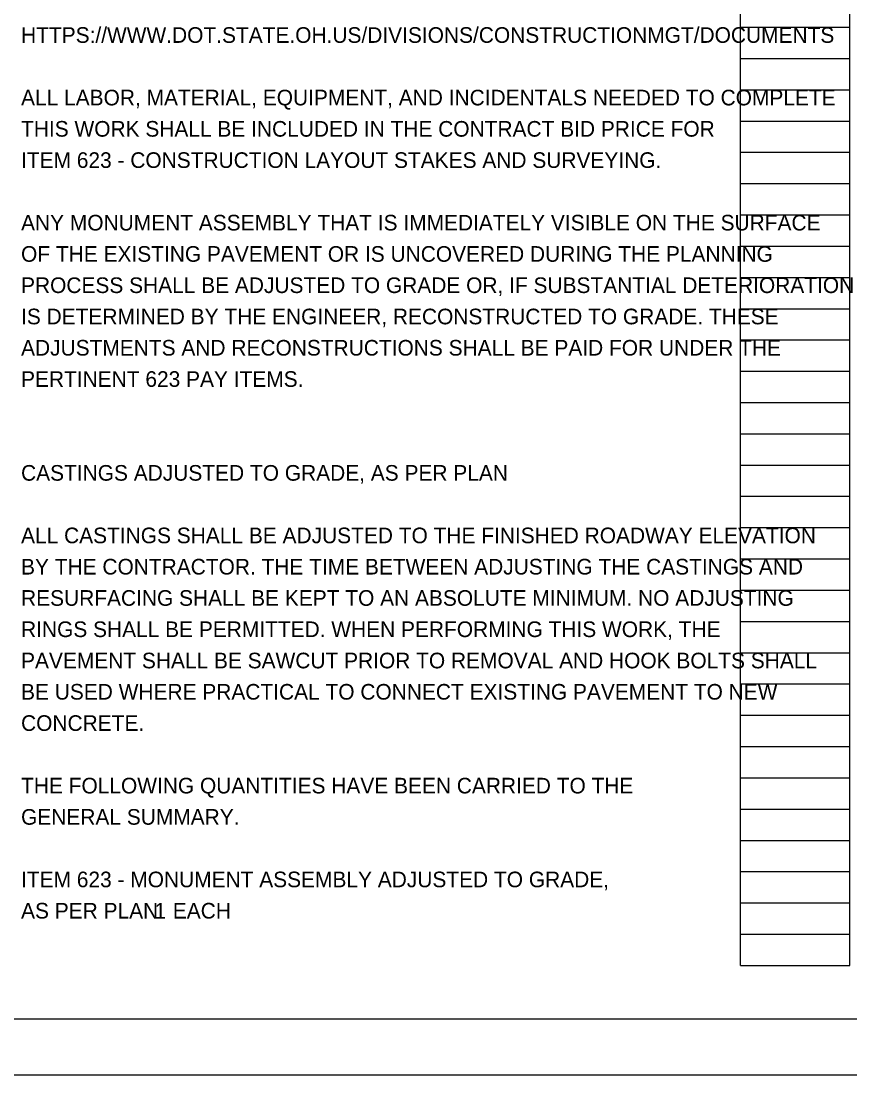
# Model space of a CAD drawing. Extents: x 0 to 63.3, y -2.5 to 22.
# Drawn here: x 17.24 to 24.66, y 0 to 9.43 of the extents above; entities that cross this region are included whole.
import ezdxf

# ---------------------------------------------------------------- set-up
doc = ezdxf.new("R2010")
doc.units = 0
for name, color, linetype in [('SH_Border', 7, 'Continuous'), ('SH_Cut_Line', 7, 'Continuous'), ('SH_Data', 7, 'Continuous'), ('SH_Text', 7, 'Continuous')]:
    doc.layers.add(name, color=color, linetype=linetype)

msp = doc.modelspace()

# ---------------------------------------------------------------- linework, layer by layer
at = {"layer": 'SH_Border'}
msp.add_lwpolyline([(1.5, 21.5), (33.5, 21.5), (33.5, 0.5), (1.5, 0.5)], close=True, dxfattribs=at)
at = {"layer": 'SH_Cut_Line'}
msp.add_lwpolyline([(0, 0), (34, 0), (34, 22), (0, 22)], close=True, dxfattribs=at)
at = {"layer": 'SH_Data'}
for p, q in [((23.68, 0.98), (23.68, 21.14)), ((24.66, 0.98), (24.66, 21.14)), ((23.68, 9.38), (24.66, 9.38)), ((23.68, 9.1), (24.66, 9.1)), ((23.68, 8.82), (24.66, 8.82)), ((23.68, 8.54), (24.66, 8.54)), ((23.68, 8.26), (24.66, 8.26)), ((23.68, 7.98), (24.66, 7.98)), ((23.68, 7.7), (24.66, 7.7)), ((23.68, 7.42), (24.66, 7.42)), ((23.68, 7.14), (24.66, 7.14)), ((23.68, 6.86), (24.66, 6.86)), ((23.68, 6.58), (24.66, 6.58)), ((23.68, 6.3), (24.66, 6.3)), ((23.68, 6.02), (24.66, 6.02)), ((23.68, 5.74), (24.66, 5.74)), ((23.68, 5.46), (24.66, 5.46)), ((23.68, 5.18), (24.66, 5.18)), ((23.68, 4.9), (24.66, 4.9)), ((23.68, 4.62), (24.66, 4.62)), ((23.68, 4.34), (24.66, 4.34)), ((23.68, 4.06), (24.66, 4.06)), ((23.68, 3.78), (24.66, 3.78)), ((23.68, 3.5), (24.66, 3.5)), ((23.68, 3.22), (24.66, 3.22)), ((23.68, 2.94), (24.66, 2.94)), ((23.68, 2.66), (24.66, 2.66)), ((23.68, 2.38), (24.66, 2.38)), ((23.68, 2.1), (24.66, 2.1)), ((23.68, 1.82), (24.66, 1.82)), ((23.68, 1.54), (24.66, 1.54)), ((23.68, 1.26), (24.66, 1.26)), ((23.68, 0.98), (24.66, 0.98))]:
    msp.add_line(p, q, dxfattribs=at)

# ---------------------------------------------------------------- texts
at = {"layer": 'SH_Text'}
for s, p in [('HTTPS://WWW.DOT.STATE.OH.US/DIVISIONS/CONSTRUCTIONMGT/DOCUMENTS', (17.24, 9.24)), ('ALL LABOR, MATERIAL, EQUIPMENT, AND INCIDENTALS NEEDED TO COMPLETE', (17.24, 8.68)), ('THIS WORK SHALL BE INCLUDED IN THE CONTRACT BID PRICE FOR ', (17.24, 8.4)), ('ITEM 623 - CONSTRUCTION LAYOUT STAKES AND SURVEYING.', (17.24, 8.12)), ('ANY MONUMENT ASSEMBLY THAT IS IMMEDIATELY VISIBLE ON THE SURFACE', (17.24, 7.56)), ('OF THE EXISTING PAVEMENT OR IS UNCOVERED DURING THE PLANNING', (17.24, 7.28)), ('PROCESS SHALL BE ADJUSTED TO GRADE OR, IF SUBSTANTIAL DETERIORATION', (17.24, 7)), ('IS DETERMINED BY THE ENGINEER, RECONSTRUCTED TO GRADE. THESE', (17.24, 6.72)), ('ADJUSTMENTS AND RECONSTRUCTIONS SHALL BE PAID FOR UNDER THE', (17.24, 6.44)), ('PERTINENT 623 PAY ITEMS.', (17.24, 6.16)), ('CASTINGS ADJUSTED TO GRADE, AS PER PLAN', (17.24, 5.32)), ('ALL CASTINGS SHALL BE ADJUSTED TO THE FINISHED ROADWAY ELEVATION', (17.24, 4.76)), ('BY THE CONTRACTOR. THE TIME BETWEEN ADJUSTING THE CASTINGS AND', (17.24, 4.48)), ('RESURFACING SHALL BE KEPT TO AN ABSOLUTE MINIMUM. NO ADJUSTING', (17.24, 4.2)), ('RINGS SHALL BE PERMITTED. WHEN PERFORMING THIS WORK, THE', (17.24, 3.92)), ('PAVEMENT SHALL BE SAWCUT PRIOR TO REMOVAL AND HOOK BOLTS SHALL', (17.24, 3.64)), ('BE USED WHERE PRACTICAL TO CONNECT EXISTING PAVEMENT TO NEW', (17.24, 3.36)), ('CONCRETE.', (17.24, 3.08)), ('THE FOLLOWING QUANTITIES HAVE BEEN CARRIED TO THE ', (17.24, 2.52)), ('GENERAL SUMMARY.', (17.24, 2.24)), ('ITEM 623 - MONUMENT ASSEMBLY ADJUSTED TO GRADE, ', (17.24, 1.68)), ('AS PER PLAN ', (17.24, 1.4)), ('1', (18.4348, 1.4)), (' EACH', (18.5465, 1.4))]:
    msp.add_text(s, height=0.14, dxfattribs=at).set_placement(p)

doc.saveas('drawing.dxf')
